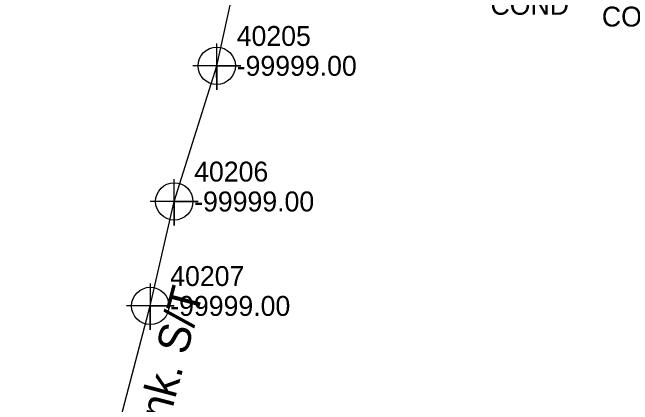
# Model space of a CAD drawing. Extents: x 2083698 to 2094313, y 743246 to 752873.
# Drawn here: x 2090827 to 2090904.8, y 744520.3 to 744569.6 of the extents above; entities that cross this region are included whole.
import ezdxf

# ---------------------------------------------------------------- set-up
doc = ezdxf.new("R2010")
doc.units = 0
for name, color, linetype in [('Exist Property Corner CELL', 7, 'Continuous'), ('Exist Right of Way Line Leader', 7, 'Continuous'), ('Exist Right of Way Line Text', 7, 'Continuous'), ('Exist Utilities Telephone UG Conduit SUE LOS B', 7, 'Continuous'), ('Exist Utilities Telephone UG Conduit SUE LOS B Text', 7, 'Continuous'), ('Scratch_Level_2', 7, 'Continuous')]:
    doc.layers.add(name, color=color, linetype=linetype)

msp = doc.modelspace()

# ---------------------------------------------------------------- linework, layer by layer
at = {"layer": 'Exist Right of Way Line Text'}
for points in [[(2090852.593, 744565.663), (2090852.626, 744559.848), (2090852.609, 744562.848), (2090855.626, 744562.848), (2090849.626, 744562.848)], [(2090847.256, 744548.63), (2090847.289, 744542.815), (2090847.272, 744545.815), (2090850.289, 744545.815), (2090844.289, 744545.815)], [(2090844.255, 744535.511), (2090844.288, 744529.696), (2090844.271, 744532.696), (2090847.288, 744532.696), (2090841.288, 744532.696)]]:
    msp.add_lwpolyline(points, dxfattribs=at)
for centre in [(2090852.626, 744562.848), (2090847.289, 744545.815), (2090844.288, 744532.696)]:
    msp.add_circle(centre, 2.344, dxfattribs=at)
at = {"layer": 'Exist Utilities Telephone UG Conduit SUE LOS B'}
msp.add_lwpolyline([(2090826.992, 744485.617), (2090829.437, 744487.68), (2090831.334, 744489.708), (2090834.431, 744496.44), (2090839.279, 744513.707), (2090844.288, 744532.696), (2090847.289, 744545.815), (2090852.626, 744562.848), (2090856.225, 744579.274), (2090861.877, 744595.472), (2090864.678, 744603.641), (2090865.786, 744607.851), (2090866.26, 744608.065)], dxfattribs=at)

# ---------------------------------------------------------------- texts
at = {"layer": 'Exist Property Corner CELL'}
for p in [(2090886.956, 744569.262), (2090900.926, 744567.782)]:
    msp.add_text('COND', height=2.5, dxfattribs=at).set_placement(p)
at = {"layer": 'Exist Right of Way Line Leader'}
for s, p in [('40205', (2090855.126, 744565.348)), ('40206', (2090849.789, 744548.315)), ('40207', (2090846.788, 744535.196))]:
    msp.add_text(s, height=2.5, dxfattribs=at).set_placement(p)
at = {"layer": 'Exist Utilities Telephone UG Conduit SUE LOS B Text'}
msp.add_text('COR-Unk. S/T', height=4, rotation=75.22288, dxfattribs=at).set_placement((2090842.168, 744501.136))
at = {"layer": 'Scratch_Level_2'}
for p in [(2090855.126, 744561.598), (2090849.789, 744544.565), (2090846.788, 744531.446)]:
    msp.add_text('-99999.00', height=2.5, dxfattribs=at).set_placement(p)

doc.saveas('drawing.dxf')
